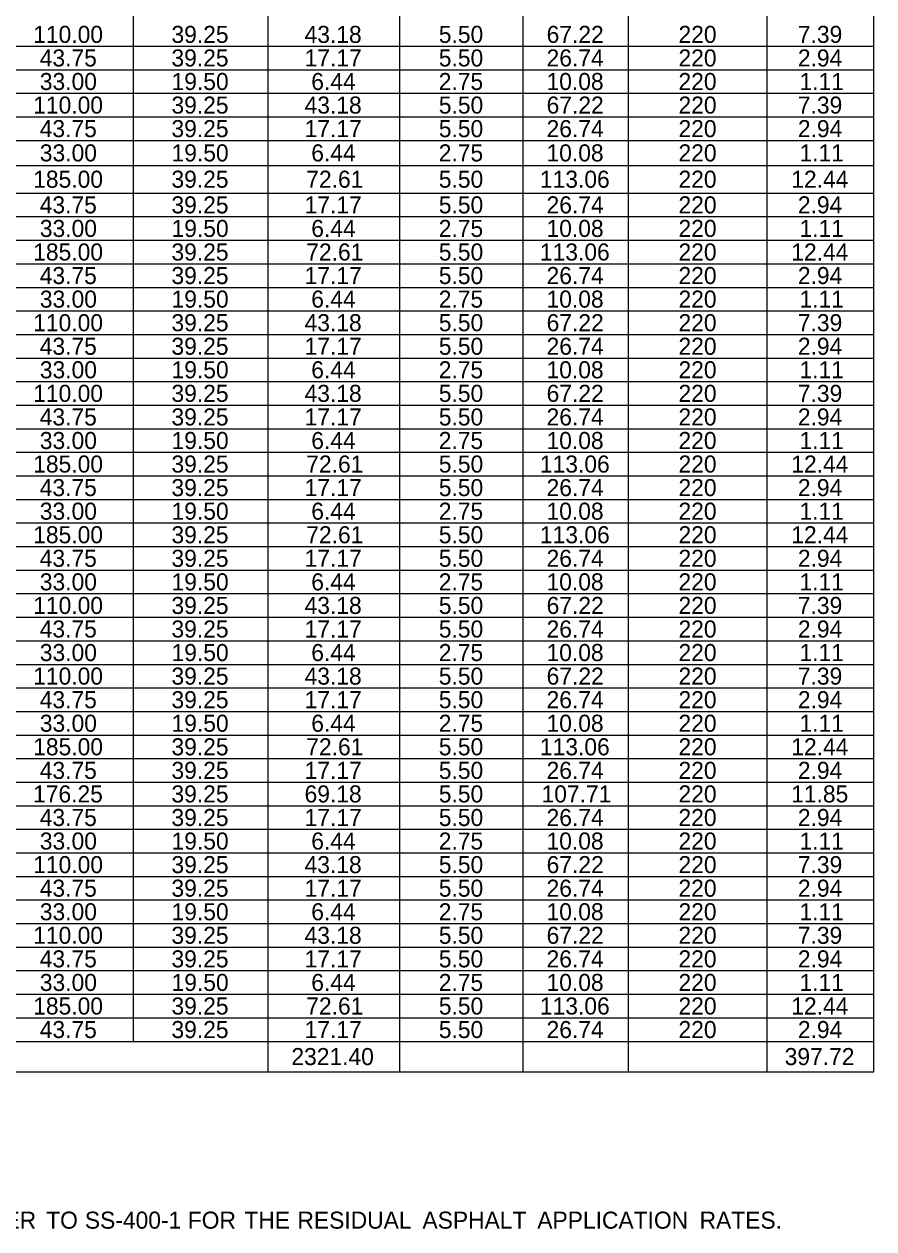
# Model space of a CAD drawing. Extents: x 544250 to 1930787, y -1948365 to 596640.
# Drawn here: x 557938.5 to 558237.3, y -1946893.5 to -1946469.8 of the extents above; entities that cross this region are included whole.
import ezdxf

# ---------------------------------------------------------------- set-up
doc = ezdxf.new("R2010")
doc.units = 0
doc.layers.add('Default', color=7, linetype='Continuous')

msp = doc.modelspace()

# ---------------------------------------------------------------- linework, layer by layer
at = {"layer": 'Default'}
for p, q in [((557976.95, -1946827.55), (557976.95, -1946062.17)), ((558070.55, -1946838.27), (558070.55, -1946062.17)), ((558237.27, -1946838.27), (558237.27, -1946062.17)), ((558024.24, -1946838.27), (558024.24, -1946088.01)), ((558113.94, -1946838.27), (558113.94, -1946088.01)), ((558150.99, -1946838.27), (558150.99, -1946088.01)), ((558199.74, -1946838.27), (558199.74, -1946088.01)), ((557760.5, -1946477.52), (558237.27, -1946477.52)), ((557760.5, -1946485.81), (558237.27, -1946485.81)), ((557760.5, -1946494.1), (558237.27, -1946494.1)), ((557760.5, -1946502.39), (558237.27, -1946502.39)), ((557760.5, -1946510.67), (558237.27, -1946510.67)), ((557760.5, -1946519.45), (558237.27, -1946519.45)), ((557760.5, -1946529.2), (558237.27, -1946529.2)), ((557554.29, -1946537.49), (558237.27, -1946537.49)), ((557760.5, -1946545.77), (558237.27, -1946545.77)), ((557760.5, -1946554.06), (558237.27, -1946554.06)), ((557760.5, -1946562.35), (558237.27, -1946562.35)), ((557760.5, -1946570.64), (558237.27, -1946570.64)), ((557760.5, -1946578.92), (558237.27, -1946578.92)), ((557760.5, -1946587.21), (558237.27, -1946587.21)), ((557760.5, -1946595.5), (558237.27, -1946595.5)), ((557760.5, -1946603.79), (558237.27, -1946603.79)), ((557760.5, -1946612.07), (558237.27, -1946612.07)), ((557760.5, -1946620.36), (558237.27, -1946620.36)), ((557760.5, -1946628.65), (558237.27, -1946628.65)), ((557554.29, -1946636.94), (558237.27, -1946636.94)), ((557760.5, -1946645.22), (558237.27, -1946645.22)), ((557760.5, -1946653.51), (558237.27, -1946653.51)), ((557760.5, -1946661.8), (558237.27, -1946661.8)), ((557760.5, -1946670.09), (558237.27, -1946670.09)), ((557760.5, -1946678.37), (558237.27, -1946678.37)), ((557760.5, -1946686.66), (558237.27, -1946686.66)), ((557760.5, -1946694.95), (558237.27, -1946694.95)), ((557760.5, -1946703.24), (558237.27, -1946703.24)), ((557760.5, -1946711.52), (558237.27, -1946711.52)), ((557760.5, -1946719.81), (558237.27, -1946719.81)), ((557760.5, -1946728.1), (558237.27, -1946728.1)), ((557554.29, -1946736.39), (558237.27, -1946736.39)), ((557760.5, -1946736.39), (558237.27, -1946736.39)), ((557760.5, -1946744.67), (558237.27, -1946744.67)), ((557760.5, -1946752.96), (558237.27, -1946752.96)), ((557760.5, -1946761.25), (558237.27, -1946761.25)), ((557760.5, -1946769.54), (558237.27, -1946769.54)), ((557760.5, -1946777.82), (558237.27, -1946777.82)), ((557760.5, -1946786.11), (558237.27, -1946786.11)), ((557760.5, -1946794.4), (558237.27, -1946794.4)), ((557760.5, -1946802.69), (558237.27, -1946802.69)), ((557760.5, -1946810.97), (558237.27, -1946810.97)), ((557760.5, -1946819.26), (558237.27, -1946819.26)), ((557554.29, -1946827.55), (558237.27, -1946827.55)), ((558024.24, -1946838.27), (558024.24, -1946827.55)), ((558113.94, -1946838.27), (558113.94, -1946827.55)), ((558150.99, -1946838.27), (558150.99, -1946827.55)), ((558199.74, -1946838.27), (558199.74, -1946827.55)), ((557554.29, -1946838.27), (558237.27, -1946838.27))]:
    msp.add_line(p, q, dxfattribs=at)

# ---------------------------------------------------------------- texts
for s, p in [('110.00', (557941.67, -1946476.38)), ('39.25', (557990.28, -1946476.38)), ('43.18', (558037.09, -1946476.38)), ('5.50', (558084.29, -1946476.38)), ('67.22', (558122.2, -1946476.38)), ('220', (558168.57, -1946476.38)), ('7.39', (558210.54, -1946476.38)), ('43.75', (557943.96, -1946484.67)), ('39.25', (557990.28, -1946484.67)), ('17.17', (558037.1, -1946484.67)), ('5.50', (558084.29, -1946484.67)), ('26.74', (558122.18, -1946484.67)), ('220', (558168.57, -1946484.67)), ('2.94', (558210.55, -1946484.67)), ('33.00', (557944, -1946492.95)), ('19.50', (557990.31, -1946492.95)), ('6.44', (558039.44, -1946492.95)), ('2.75', (558084.26, -1946492.95)), ('10.08', (558122.16, -1946492.95)), ('220', (558168.57, -1946492.95)), ('1.11', (558211.12, -1946492.95)), ('110.00', (557941.67, -1946501.24)), ('39.25', (557990.28, -1946501.24)), ('43.18', (558037.09, -1946501.24)), ('5.50', (558084.29, -1946501.24)), ('67.22', (558122.2, -1946501.24)), ('220', (558168.57, -1946501.24)), ('7.39', (558210.54, -1946501.24)), ('43.75', (557943.96, -1946509.53)), ('39.25', (557990.28, -1946509.53)), ('17.17', (558037.1, -1946509.53)), ('5.50', (558084.29, -1946509.53)), ('26.74', (558122.18, -1946509.53)), ('220', (558168.57, -1946509.53)), ('2.94', (558210.55, -1946509.53)), ('33.00', (557944, -1946518.06)), ('19.50', (557990.31, -1946518.06)), ('6.44', (558039.44, -1946518.06)), ('2.75', (558084.26, -1946518.06)), ('10.08', (558122.16, -1946518.06)), ('220', (558168.57, -1946518.06)), ('1.11', (558211.12, -1946518.06)), ('185.00', (557941.67, -1946527.32)), ('39.25', (557990.28, -1946527.32)), ('72.61', (558037.68, -1946527.32)), ('5.50', (558084.29, -1946527.32)), ('113.06', (558119.84, -1946527.32)), ('220', (558168.57, -1946527.32)), ('12.44', (558208.22, -1946527.32)), ('43.75', (557943.96, -1946536.34)), ('39.25', (557990.28, -1946536.34)), ('17.17', (558037.1, -1946536.34)), ('5.50', (558084.29, -1946536.34)), ('26.74', (558122.18, -1946536.34)), ('220', (558168.57, -1946536.34)), ('2.94', (558210.55, -1946536.34)), ('33.00', (557944, -1946544.63)), ('19.50', (557990.31, -1946544.63)), ('6.44', (558039.44, -1946544.63)), ('2.75', (558084.26, -1946544.63)), ('10.08', (558122.16, -1946544.63)), ('220', (558168.57, -1946544.63)), ('1.11', (558211.12, -1946544.63)), ('185.00', (557941.67, -1946552.92)), ('39.25', (557990.28, -1946552.92)), ('72.61', (558037.68, -1946552.92)), ('5.50', (558084.29, -1946552.92)), ('113.06', (558119.84, -1946552.92)), ('220', (558168.57, -1946552.92)), ('12.44', (558208.22, -1946552.92)), ('43.75', (557943.96, -1946561.2)), ('39.25', (557990.28, -1946561.2)), ('17.17', (558037.1, -1946561.2)), ('5.50', (558084.29, -1946561.2)), ('26.74', (558122.18, -1946561.2)), ('220', (558168.57, -1946561.2)), ('2.94', (558210.55, -1946561.2)), ('33.00', (557944, -1946569.49)), ('19.50', (557990.31, -1946569.49)), ('6.44', (558039.44, -1946569.49)), ('2.75', (558084.26, -1946569.49)), ('10.08', (558122.16, -1946569.49)), ('220', (558168.57, -1946569.49)), ('1.11', (558211.12, -1946569.49)), ('110.00', (557941.67, -1946577.78)), ('39.25', (557990.28, -1946577.78)), ('43.18', (558037.09, -1946577.78)), ('5.50', (558084.29, -1946577.78)), ('67.22', (558122.2, -1946577.78)), ('220', (558168.57, -1946577.78)), ('7.39', (558210.54, -1946577.78)), ('43.75', (557943.96, -1946586.07)), ('39.25', (557990.28, -1946586.07)), ('17.17', (558037.1, -1946586.07)), ('5.50', (558084.29, -1946586.07)), ('26.74', (558122.18, -1946586.07)), ('220', (558168.57, -1946586.07)), ('2.94', (558210.55, -1946586.07)), ('33.00', (557944, -1946594.35)), ('19.50', (557990.31, -1946594.35)), ('6.44', (558039.44, -1946594.35)), ('2.75', (558084.26, -1946594.35)), ('10.08', (558122.16, -1946594.35)), ('220', (558168.57, -1946594.35)), ('1.11', (558211.12, -1946594.35)), ('110.00', (557941.67, -1946602.64)), ('39.25', (557990.28, -1946602.64)), ('43.18', (558037.09, -1946602.64)), ('5.50', (558084.29, -1946602.64)), ('67.22', (558122.2, -1946602.64)), ('220', (558168.57, -1946602.64)), ('7.39', (558210.54, -1946602.64)), ('43.75', (557943.96, -1946610.93)), ('39.25', (557990.28, -1946610.93)), ('17.17', (558037.1, -1946610.93)), ('5.50', (558084.29, -1946610.93)), ('26.74', (558122.18, -1946610.93)), ('220', (558168.57, -1946610.93)), ('2.94', (558210.55, -1946610.93)), ('33.00', (557944, -1946619.22)), ('19.50', (557990.31, -1946619.22)), ('6.44', (558039.44, -1946619.22)), ('2.75', (558084.26, -1946619.22)), ('10.08', (558122.16, -1946619.22)), ('220', (558168.57, -1946619.22)), ('1.11', (558211.12, -1946619.22)), ('185.00', (557941.67, -1946627.5)), ('39.25', (557990.28, -1946627.5)), ('72.61', (558037.68, -1946627.5)), ('5.50', (558084.29, -1946627.5)), ('113.06', (558119.84, -1946627.5)), ('220', (558168.57, -1946627.5)), ('12.44', (558208.22, -1946627.5)), ('43.75', (557943.96, -1946635.79)), ('39.25', (557990.28, -1946635.79)), ('17.17', (558037.1, -1946635.79)), ('5.50', (558084.29, -1946635.79)), ('26.74', (558122.18, -1946635.79)), ('220', (558168.57, -1946635.79)), ('2.94', (558210.55, -1946635.79)), ('33.00', (557944, -1946644.08)), ('19.50', (557990.31, -1946644.08)), ('6.44', (558039.44, -1946644.08)), ('2.75', (558084.26, -1946644.08)), ('10.08', (558122.16, -1946644.08)), ('220', (558168.57, -1946644.08)), ('1.11', (558211.12, -1946644.08)), ('185.00', (557941.67, -1946652.37)), ('39.25', (557990.28, -1946652.37)), ('72.61', (558037.68, -1946652.37)), ('5.50', (558084.29, -1946652.37)), ('113.06', (558119.84, -1946652.37)), ('220', (558168.57, -1946652.37)), ('12.44', (558208.22, -1946652.37)), ('43.75', (557943.96, -1946660.65)), ('39.25', (557990.28, -1946660.65)), ('17.17', (558037.1, -1946660.65)), ('5.50', (558084.29, -1946660.65)), ('26.74', (558122.18, -1946660.65)), ('220', (558168.57, -1946660.65)), ('2.94', (558210.55, -1946660.65)), ('33.00', (557944, -1946668.94)), ('19.50', (557990.31, -1946668.94)), ('6.44', (558039.44, -1946668.94)), ('2.75', (558084.26, -1946668.94)), ('10.08', (558122.16, -1946668.94)), ('220', (558168.57, -1946668.94)), ('1.11', (558211.12, -1946668.94)), ('110.00', (557941.67, -1946677.23)), ('39.25', (557990.28, -1946677.23)), ('43.18', (558037.09, -1946677.23)), ('5.50', (558084.29, -1946677.23)), ('67.22', (558122.2, -1946677.23)), ('220', (558168.57, -1946677.23)), ('7.39', (558210.54, -1946677.23)), ('43.75', (557943.96, -1946685.52)), ('39.25', (557990.28, -1946685.52)), ('17.17', (558037.1, -1946685.52)), ('5.50', (558084.29, -1946685.52)), ('26.74', (558122.18, -1946685.52)), ('220', (558168.57, -1946685.52)), ('2.94', (558210.55, -1946685.52)), ('33.00', (557944, -1946693.8)), ('19.50', (557990.31, -1946693.8)), ('6.44', (558039.44, -1946693.8)), ('2.75', (558084.26, -1946693.8)), ('10.08', (558122.16, -1946693.8)), ('220', (558168.57, -1946693.8)), ('1.11', (558211.12, -1946693.8)), ('110.00', (557941.67, -1946702.09)), ('39.25', (557990.28, -1946702.09)), ('43.18', (558037.09, -1946702.09)), ('5.50', (558084.29, -1946702.09)), ('67.22', (558122.2, -1946702.09)), ('220', (558168.57, -1946702.09)), ('7.39', (558210.54, -1946702.09)), ('43.75', (557943.96, -1946710.38)), ('39.25', (557990.28, -1946710.38)), ('17.17', (558037.1, -1946710.38)), ('5.50', (558084.29, -1946710.38)), ('26.74', (558122.18, -1946710.38)), ('220', (558168.57, -1946710.38)), ('2.94', (558210.55, -1946710.38)), ('33.00', (557944, -1946718.67)), ('19.50', (557990.31, -1946718.67)), ('6.44', (558039.44, -1946718.67)), ('2.75', (558084.26, -1946718.67)), ('10.08', (558122.16, -1946718.67)), ('220', (558168.57, -1946718.67)), ('1.11', (558211.12, -1946718.67)), ('185.00', (557941.67, -1946726.95)), ('39.25', (557990.28, -1946726.95)), ('72.61', (558037.68, -1946726.95)), ('5.50', (558084.29, -1946726.95)), ('113.06', (558119.84, -1946726.95)), ('220', (558168.57, -1946726.95)), ('12.44', (558208.22, -1946726.95)), ('43.75', (557943.96, -1946735.24)), ('39.25', (557990.28, -1946735.24)), ('17.17', (558037.1, -1946735.24)), ('5.50', (558084.29, -1946735.24)), ('26.74', (558122.18, -1946735.24)), ('220', (558168.57, -1946735.24)), ('2.94', (558210.55, -1946735.24)), ('176.25', (557941.63, -1946743.53)), ('39.25', (557990.28, -1946743.53)), ('69.18', (558037.09, -1946743.53)), ('5.50', (558084.29, -1946743.53)), ('107.71', (558120.42, -1946743.53)), ('220', (558168.57, -1946743.53)), ('11.85', (558208.19, -1946743.53)), ('43.75', (557943.96, -1946751.82)), ('39.25', (557990.28, -1946751.82)), ('17.17', (558037.1, -1946751.82)), ('5.50', (558084.29, -1946751.82)), ('26.74', (558122.18, -1946751.82)), ('220', (558168.57, -1946751.82)), ('2.94', (558210.55, -1946751.82)), ('33.00', (557944, -1946760.1)), ('19.50', (557990.31, -1946760.1)), ('6.44', (558039.44, -1946760.1)), ('2.75', (558084.26, -1946760.1)), ('10.08', (558122.16, -1946760.1)), ('220', (558168.57, -1946760.1)), ('1.11', (558211.12, -1946760.1)), ('110.00', (557941.67, -1946768.39)), ('39.25', (557990.28, -1946768.39)), ('43.18', (558037.09, -1946768.39)), ('5.50', (558084.29, -1946768.39)), ('67.22', (558122.2, -1946768.39)), ('220', (558168.57, -1946768.39)), ('7.39', (558210.54, -1946768.39)), ('43.75', (557943.96, -1946776.68)), ('39.25', (557990.28, -1946776.68)), ('17.17', (558037.1, -1946776.68)), ('5.50', (558084.29, -1946776.68)), ('26.74', (558122.18, -1946776.68)), ('220', (558168.57, -1946776.68)), ('2.94', (558210.55, -1946776.68)), ('33.00', (557944, -1946784.97)), ('19.50', (557990.31, -1946784.97)), ('6.44', (558039.44, -1946784.97)), ('2.75', (558084.26, -1946784.97)), ('10.08', (558122.16, -1946784.97)), ('220', (558168.57, -1946784.97)), ('1.11', (558211.12, -1946784.97)), ('110.00', (557941.67, -1946793.25)), ('39.25', (557990.28, -1946793.25)), ('43.18', (558037.09, -1946793.25)), ('5.50', (558084.29, -1946793.25)), ('67.22', (558122.2, -1946793.25)), ('220', (558168.57, -1946793.25)), ('7.39', (558210.54, -1946793.25)), ('43.75', (557943.96, -1946801.54)), ('39.25', (557990.28, -1946801.54)), ('17.17', (558037.1, -1946801.54)), ('5.50', (558084.29, -1946801.54)), ('26.74', (558122.18, -1946801.54)), ('220', (558168.57, -1946801.54)), ('2.94', (558210.55, -1946801.54)), ('33.00', (557944, -1946809.83)), ('19.50', (557990.31, -1946809.83)), ('6.44', (558039.44, -1946809.83)), ('2.75', (558084.26, -1946809.83)), ('10.08', (558122.16, -1946809.83)), ('220', (558168.57, -1946809.83)), ('1.11', (558211.12, -1946809.83)), ('185.00', (557941.67, -1946818.12)), ('39.25', (557990.28, -1946818.12)), ('72.61', (558037.68, -1946818.12)), ('5.50', (558084.29, -1946818.12)), ('113.06', (558119.84, -1946818.12)), ('220', (558168.57, -1946818.12)), ('12.44', (558208.22, -1946818.12)), ('43.75', (557943.96, -1946826.4)), ('39.25', (557990.28, -1946826.4)), ('17.17', (558037.1, -1946826.4)), ('5.50', (558084.29, -1946826.4)), ('26.74', (558122.18, -1946826.4)), ('220', (558168.57, -1946826.4)), ('2.94', (558210.55, -1946826.4)), ('2321.40', (558032.45, -1946835.91)), ('397.72', (558205.9, -1946835.91)), ('  REFER', (557911.04, -1946893.44)), (' TO', (557944, -1946893.44)), (' SS-400-1', (557957.6, -1946893.44)), (' FOR', (557993.79, -1946893.44)), (' THE', (558013.7, -1946893.44)), (' RESIDUAL', (558032.35, -1946893.44)), (' ASPHALT', (558076.31, -1946893.44)), (' APPLICATION', (558116.68, -1946893.44)), (' RATES.', (558173.76, -1946893.44))]:
    msp.add_text(s, height=6, dxfattribs=at).set_placement(p)

doc.saveas('drawing.dxf')
